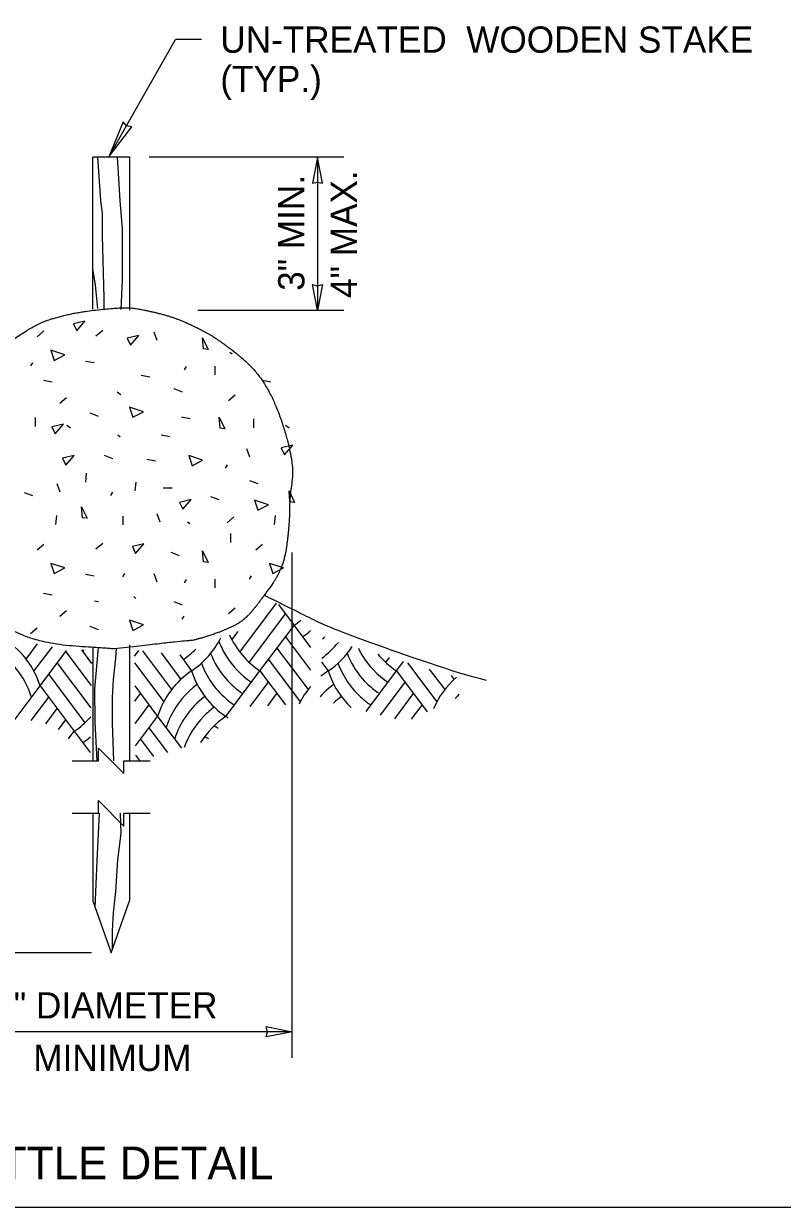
# Model space of a CAD drawing. Extents: x 99862 to 103680, y 99470 to 102076.
# Drawn here: x 100379 to 100841, y 100000 to 100721 of the extents above; entities that cross this region are included whole.
import ezdxf

# ---------------------------------------------------------------- set-up
doc = ezdxf.new("R2010")
doc.units = 0
for name, color, linetype in [('Level 1', 7, 'Continuous'), ('Level 13', 7, 'Continuous'), ('Level 15', 7, 'Continuous'), ('Level 2', 7, 'Continuous'), ('Level 20', 7, 'Continuous'), ('Level 4', 7, 'Continuous')]:
    doc.layers.add(name, color=color, linetype=linetype)

msp = doc.modelspace()

# ---------------------------------------------------------------- linework, layer by layer
at = {"layer": 'Level 1'}
msp.add_lwpolyline([(99862, 99999.5), (103151, 99999.5), (103151, 102075.5), (99862, 102075.5)], close=True, dxfattribs=at)
at = {"layer": 'Level 13'}
for p, q in [((100510.74, 100337.71), (100533.08, 100367.48)), ((100534.27, 100366.66), (100543.76, 100354.01)), ((100516.45, 100331.46), (100538.56, 100360.94)), ((100505.92, 100345.14), (100509.76, 100350.26)), ((100522.97, 100326.29), (100543.76, 100354.01)), ((100543.76, 100354.01), (100553.86, 100340.53)), ((100380.55, 100333.49), (100387.53, 100342.8)), ((100385.37, 100326.06), (100396.57, 100341)), ((100538.56, 100347.08), (100553.86, 100326.67)), ((100389.11, 100317.19), (100405.2, 100338.64)), ((100404.7, 100337.98), (100420.22, 100317.3)), ((100414.27, 100339.08), (100420.43, 100330.87)), ((100446.51, 100335.22), (100449.18, 100338.78)), ((100451.42, 100338.53), (100469.17, 100314.87)), ((100462.76, 100337.27), (100474.87, 100321.12)), ((100474.1, 100336.01), (100481.39, 100326.29)), ((100533.36, 100340.15), (100552.32, 100314.87)), ((100599.61, 100331.46), (100601.88, 100334.48)), ((100399.51, 100331.05), (100420, 100303.72)), ((100446.55, 100331.16), (100464.35, 100307.44)), ((100528.17, 100333.22), (100547.5, 100307.44)), ((100560.51, 100331.67), (100564.55, 100326.29)), ((100606.12, 100326.29), (100610.39, 100331.98)), ((100612.78, 100331.28), (100630.66, 100307.44)), ((100626.12, 100327.35), (100635.48, 100314.87)), ((100394.31, 100324.12), (100416.42, 100294.65)), ((100502.18, 100298.57), (100522.97, 100326.29)), ((100517.04, 100304.53), (100528.17, 100319.36)), ((100522.97, 100326.29), (100538.46, 100305.63)), ((100587.63, 100301.63), (100606.12, 100326.29)), ((100596.35, 100299.4), (100611.32, 100319.36)), ((100606.12, 100326.29), (100624.83, 100301.34)), ((100639.45, 100323.42), (100641.19, 100321.12)), ((100371.98, 100294.36), (100389.11, 100317.19)), ((100389.11, 100317.19), (100409.9, 100289.47)), ((100446.7, 100317.1), (100460.6, 100298.57)), ((100446.8, 100307.88), (100450.21, 100312.43)), ((100527.86, 100305.09), (100533.36, 100312.43)), ((100606.12, 100298.57), (100616.52, 100312.43)), ((100383.59, 100295.97), (100394.31, 100310.26)), ((100450.21, 100298.57), (100455.4, 100305.5)), ((100616.52, 100298.57), (100621.72, 100305.5)), ((100392.56, 100294.07), (100399.51, 100303.33)), ((100446.94, 100294.22), (100450.21, 100298.57)), ((100447.09, 100280.55), (100460.6, 100298.57)), ((100460.6, 100298.57), (100475.18, 100279.14)), ((100605.08, 100297.17), (100606.12, 100298.57)), ((100615.3, 100296.94), (100616.52, 100298.57)), ((100400.28, 100290.5), (100404.7, 100296.4)), ((100455.4, 100291.64), (100466.69, 100276.59)), ((100406.41, 100284.82), (100409.9, 100289.47)), ((100409.9, 100289.47), (100419.58, 100276.57)), ((100450.21, 100284.71), (100458.21, 100274.04)), ((100447.15, 100274.93), (100449.58, 100271.69))]:
    msp.add_line(p, q, dxfattribs=at)
for centre, start, end in [((100514.41, 100397.67), 303.90361, 309.64609), ((100552.31, 100369.95), 204.24471, 236.09639), ((100519.61, 100390.74), 303.90361, 310.62757), ((100338.98, 100301.25), 17.6434, 56.09639), ((100452.05, 100369.95), 303.90361, 333.41153), ((100547.12, 100363.02), 200.87781, 211.33197), ((100530, 100376.88), 305.57834, 320.80666), ((100524.81, 100383.81), 313.63976, 315.83303), ((100535.2, 100369.95), 303.90361, 326.80593), ((100333.78, 100294.32), 17.6434, 48.95975), ((100465.23, 100322.04), 161.09911, 162.3566), ((100446.85, 100376.88), 303.90361, 314.86242), ((100541.92, 100356.09), 201.43438, 220.94161), ((100547.12, 100363.02), 211.33188, 236.09639), ((100625.07, 100356.09), 201.43438, 220.94161), ((100630.27, 100363.02), 205.88324, 211.33197), ((100630.27, 100363.02), 211.33188, 236.09639), ((100635.47, 100369.95), 219.39613, 236.09639), ((100470.43, 100315.11), 161.84764, 162.3566), ((100536.72, 100349.16), 200.24322, 228.95992), ((100619.88, 100349.16), 200.24322, 228.95992), ((100510.74, 100282.62), 123.90361, 162.3566), ((100531.52, 100342.23), 197.6434, 236.09639), ((100541.92, 100356.09), 220.94154, 236.09639), ((100593.89, 100282.62), 123.90361, 129.91543), ((100614.68, 100342.23), 197.6434, 226.71979), ((100625.07, 100356.09), 220.94154, 236.09639), ((100677.05, 100282.62), 130.76183, 157.12727), ((100515.93, 100275.69), 126.30625, 154.2266), ((100593.89, 100282.62), 139.53727, 153.53859), ((100599.09, 100275.69), 126.30625, 138.64934), ((100521.13, 100268.76), 127.1006, 145.49109), ((100536.72, 100349.16), 228.95986, 236.09639), ((100604.29, 100268.76), 127.1006, 133.87218), ((100619.88, 100349.16), 228.95986, 236.09639), ((100682.24, 100275.69), 136.30424, 140.20496), ((100380.56, 100333.14), 303.90361, 318.4378), ((100515.93, 100275.69), 154.22654, 162.3566), ((100521.13, 100268.76), 145.49102, 162.3566), ((100526.33, 100261.83), 135.71269, 160.22849), ((100531.52, 100254.9), 123.90361, 148.19583), ((100526.33, 100261.83), 126.331, 135.71278), ((100472.83, 100254.9), 54.1392, 56.09634), ((100609.48, 100261.83), 126.331, 126.61289), ((100467.64, 100247.97), 55.25432, 58.54646), ((100385.75, 100326.21), 303.90361, 310.22759), ((100462.44, 100241.05), 56.37289, 59.30215)]:
    msp.add_arc(centre, 52.61, start, end, dxfattribs=at)
msp.add_open_spline([(100660.97, 100320.37), (100641.53, 100325.21), (100579.75, 100347.1), (100558.59, 100355.49), (100544.07, 100363.27), (100525.77, 100372.29)], degree=3, dxfattribs=at)
at = {"layer": 'Level 15'}
for p, q in [((100430.86, 100639.45), (100471.46, 100710.83)), ((100487.46, 100710.83), (100471.46, 100710.83)), ((100455.52, 100639.45), (100574.05, 100639.45)), ((100455.52, 100639.45), (100574.05, 100639.45)), ((100558.06, 100639.08), (100558.06, 100545.93)), ((100558.06, 100639.08), (100558.06, 100545.93)), ((100485.09, 100545.93), (100574.05, 100545.93)), ((100485.09, 100545.93), (100574.05, 100545.93)), ((100542.55, 100090.53), (100542.55, 100398.42)), ((100420.38, 100154.53), (100187.86, 100154.53)), ((100320.2, 100106.53), (100542.55, 100106.53))]:
    msp.add_line(p, q, dxfattribs=at)
for points in [[(100430.86, 100639.45), (100444.86, 100657.72), (100441.74, 100658.3), (100439.69, 100660.71)], [(100558.06, 100639.08), (100554.97, 100623.36), (100558.06, 100624.08), (100561.14, 100623.36)], [(100558.06, 100639.08), (100554.97, 100623.36), (100558.06, 100624.08), (100561.14, 100623.36)], [(100558.06, 100545.93), (100554.97, 100561.65), (100558.06, 100560.92), (100561.14, 100561.65)], [(100558.06, 100545.93), (100554.97, 100561.65), (100558.06, 100560.92), (100561.14, 100561.65)], [(100542.55, 100106.5), (100526.82, 100103.41), (100527.55, 100106.5), (100526.82, 100109.58)]]:
    msp.add_lwpolyline(points, close=True, dxfattribs=at)
for points in [[(100408.64, 100271.52), (100424.64, 100271.52), (100424.64, 100279.27), (100440.12, 100263.78), (100440.12, 100271.52), (100456.12, 100271.52)], [(100408.64, 100239.52), (100424.64, 100239.52), (100424.64, 100247.27), (100440.12, 100231.78), (100440.12, 100239.52), (100456.12, 100239.52)]]:
    msp.add_lwpolyline(points, dxfattribs=at)
at = {"layer": 'Level 2'}
for p, q in [((100387.28, 100529.82), (100391.38, 100533.34)), ((100387.28, 100529.82), (100391.38, 100533.34)), ((100423.1, 100530.37), (100427.2, 100533.88)), ((100423.1, 100530.37), (100427.2, 100533.88)), ((100460.39, 100527.48), (100458.58, 100532.57)), ((100460.39, 100527.48), (100458.58, 100532.57)), ((100384.47, 100513.99), (100383.34, 100512.02)), ((100384.47, 100513.99), (100383.34, 100512.02)), ((100416.69, 100515.05), (100422.01, 100514.08)), ((100416.69, 100515.05), (100422.01, 100514.08)), ((100504.67, 100520.47), (100506.08, 100519.34)), ((100504.67, 100520.47), (100506.08, 100519.34)), ((100477.95, 100511.74), (100476.82, 100509.77)), ((100477.95, 100511.74), (100476.82, 100509.77)), ((100495.54, 100511.99), (100495.54, 100506.59)), ((100495.54, 100511.99), (100495.54, 100506.59)), ((100391.19, 100503.37), (100396.5, 100502.4)), ((100391.19, 100503.37), (100396.5, 100502.4)), ((100450.61, 100506.36), (100455.93, 100505.39)), ((100450.61, 100506.36), (100455.93, 100505.39)), ((100524.34, 100503.37), (100529.65, 100502.4)), ((100524.34, 100503.37), (100529.65, 100502.4)), ((100401.12, 100489.36), (100405.22, 100492.88)), ((100401.12, 100489.36), (100405.22, 100492.88)), ((100435.95, 100496.26), (100438.2, 100494.57)), ((100435.95, 100496.26), (100438.2, 100494.57)), ((100470.61, 100498.33), (100475.63, 100496.32)), ((100470.61, 100498.33), (100475.63, 100496.32)), ((100503.88, 100490.99), (100507.98, 100494.51)), ((100503.88, 100490.99), (100507.98, 100494.51)), ((100386, 100480.54), (100386, 100475.14)), ((100386, 100480.54), (100386, 100475.14)), ((100419.41, 100483.4), (100424.43, 100481.39)), ((100419.41, 100483.4), (100424.43, 100481.39)), ((100475.13, 100480.98), (100480.44, 100480.01)), ((100475.13, 100480.98), (100480.44, 100480.01)), ((100519.15, 100479.79), (100519.15, 100474.39)), ((100519.15, 100479.79), (100519.15, 100474.39)), ((100405.29, 100475.99), (100407.54, 100474.3)), ((100405.29, 100475.99), (100407.54, 100474.3)), ((100538.44, 100475.99), (100540.69, 100474.3)), ((100436.51, 100470.07), (100437.92, 100468.95)), ((100436.51, 100470.07), (100437.92, 100468.95)), ((100462.74, 100470.02), (100468.05, 100469.06)), ((100462.74, 100470.02), (100468.05, 100469.06)), ((100428.1, 100457.6), (100433.11, 100455.59)), ((100428.1, 100457.6), (100433.11, 100455.59)), ((100516.74, 100456.46), (100514.92, 100461.55)), ((100516.74, 100456.46), (100514.92, 100461.55)), ((100454.08, 100455.31), (100459.39, 100454.34)), ((100454.08, 100455.31), (100459.39, 100454.34)), ((100502.99, 100451.77), (100501.86, 100449.8)), ((100502.99, 100451.77), (100501.86, 100449.8)), ((100417.22, 100446.7), (100416.69, 100441.33)), ((100417.22, 100446.7), (100416.69, 100441.33)), ((100516.58, 100442.19), (100521.66, 100440.38)), ((100516.58, 100442.19), (100521.66, 100440.38)), ((100379.32, 100434.85), (100384.41, 100433.03)), ((100379.32, 100434.85), (100384.41, 100433.03)), ((100401.27, 100435.14), (100399.46, 100440.23)), ((100401.27, 100435.14), (100399.46, 100440.23)), ((100433.14, 100435.15), (100432.01, 100433.18)), ((100433.14, 100435.15), (100432.01, 100433.18)), ((100447.49, 100441.3), (100446.82, 100435.94)), ((100447.49, 100441.3), (100446.82, 100435.94)), ((100464.07, 100437.86), (100469.47, 100437.86)), ((100464.07, 100437.86), (100469.47, 100437.86)), ((100492.86, 100432.61), (100497.88, 100430.61)), ((100492.86, 100432.61), (100497.88, 100430.61)), ((100399.04, 100420.91), (100398.51, 100415.53)), ((100399.04, 100420.91), (100398.51, 100415.53)), ((100439.49, 100420.58), (100439.49, 100415.18)), ((100439.49, 100420.58), (100439.49, 100415.18)), ((100462.21, 100416.96), (100460.39, 100422.05)), ((100462.21, 100416.96), (100460.39, 100422.05)), ((100532.19, 100420.91), (100531.66, 100415.53)), ((100532.19, 100420.91), (100531.66, 100415.53)), ((100478.79, 100417.13), (100480.2, 100416.01)), ((100478.79, 100417.13), (100480.2, 100416.01)), ((100503.11, 100416.48), (100507.06, 100420.15)), ((100503.11, 100416.48), (100507.06, 100420.15)), ((100505.04, 100409.89), (100505.04, 100404.49)), ((100505.04, 100409.89), (100505.04, 100404.49)), ((100387.28, 100400.03), (100391.38, 100403.54)), ((100387.28, 100400.03), (100391.38, 100403.54)), ((100423.1, 100400.57), (100427.2, 100404.08)), ((100423.1, 100400.57), (100427.2, 100404.08)), ((100468.71, 100398.67), (100473.73, 100396.67)), ((100468.71, 100398.67), (100473.73, 100396.67)), ((100520.43, 100400.03), (100524.53, 100403.54)), ((100520.43, 100400.03), (100524.53, 100403.54)), ((100416.69, 100385.25), (100422.01, 100384.28)), ((100416.69, 100385.25), (100422.01, 100384.28)), ((100440.45, 100385.6), (100439.33, 100383.63)), ((100440.45, 100385.6), (100439.33, 100383.63)), ((100460.39, 100380.24), (100458.58, 100385.32)), ((100460.39, 100380.24), (100458.58, 100385.32)), ((100517.62, 100384.19), (100516.49, 100382.22)), ((100517.62, 100384.19), (100516.49, 100382.22)), ((100477.95, 100381.94), (100476.82, 100379.97)), ((100477.95, 100381.94), (100476.82, 100379.97)), ((100495.54, 100382.2), (100495.54, 100376.8)), ((100495.54, 100382.2), (100495.54, 100376.8)), ((100391.19, 100373.57), (100396.5, 100372.61)), ((100391.19, 100373.57), (100396.5, 100372.61)), ((100446.08, 100371.53), (100447.49, 100370.4)), ((100446.08, 100371.53), (100447.49, 100370.4)), ((100401.12, 100359.57), (100405.22, 100363.08)), ((100401.12, 100359.57), (100405.22, 100363.08)), ((100424.7, 100368.43), (100422.17, 100368.71)), ((100424.7, 100368.43), (100422.17, 100368.71)), ((100470.61, 100368.53), (100475.63, 100366.53)), ((100470.61, 100368.53), (100475.63, 100366.53)), ((100503.88, 100361.2), (100507.98, 100364.71)), ((100503.88, 100361.2), (100507.98, 100364.71)), ((100476.54, 100359.7), (100475.41, 100357.73)), ((100476.54, 100359.7), (100475.41, 100357.73)), ((100383.18, 100349.09), (100387.28, 100352.6)), ((100383.18, 100349.09), (100387.28, 100352.6)), ((100419.41, 100353.6), (100424.43, 100351.59)), ((100419.41, 100353.6), (100424.43, 100351.59)), ((100443.52, 100342.09), (100443.52, 100271.52)), ((100443.52, 100342.09), (100443.52, 100271.52)), ((100421.24, 100340.82), (100421.24, 100271.52)), ((100421.24, 100340.82), (100421.24, 100271.52)), ((100421.24, 100239.52), (100421.24, 100186.23)), ((100421.24, 100239.52), (100421.24, 100186.23)), ((100443.52, 100239.52), (100443.52, 100186.23)), ((100443.52, 100239.52), (100443.52, 100186.23)), ((100421.24, 100186.23), (100432.38, 100154.53)), ((100432.38, 100154.53), (100443.52, 100186.23))]:
    msp.add_line(p, q, dxfattribs=at)
for points in [[(100421.24, 100546.63), (100421.24, 100639.45), (100443.52, 100639.45), (100443.52, 100545.93)], [(100421.24, 100546.63), (100421.24, 100639.45), (100443.52, 100639.45), (100443.52, 100545.93)], [(100426.04, 100612.77), (100424.22, 100639.45)], [(100426.04, 100612.77), (100424.22, 100639.45)], [(100437.89, 100612.77), (100436.31, 100639.45)], [(100437.89, 100612.77), (100436.31, 100639.45)], [(100428.02, 100547.1), (100428.02, 100553.44), (100427.08, 100591.33), (100427.08, 100604.82), (100426.04, 100612.77)], [(100428.02, 100547.1), (100428.02, 100553.44), (100427.08, 100591.33), (100427.08, 100604.82), (100426.04, 100612.77)], [(100438.38, 100546.52), (100439.3, 100564.34), (100439.3, 100595.48), (100437.89, 100612.77)], [(100438.38, 100546.52), (100439.3, 100564.34), (100439.3, 100595.48), (100437.89, 100612.77)], [(100424.21, 100546.94), (100422.84, 100561.22), (100421.24, 100571.24)], [(100424.21, 100546.94), (100422.84, 100561.22), (100421.24, 100571.24)], [(100422.72, 100294.75), (100422.37, 100315.28), (100424.71, 100340.57)], [(100422.72, 100294.75), (100422.37, 100315.28), (100424.71, 100340.57)], [(100434.01, 100271.52), (100433.24, 100294.52), (100433.24, 100310.09), (100433.71, 100320.99), (100435.12, 100333.97), (100435.57, 100340.09)], [(100434.01, 100271.52), (100433.24, 100294.52), (100433.24, 100310.09), (100433.71, 100320.99), (100435.12, 100333.97), (100435.57, 100340.09)], [(100423.93, 100271.52), (100422.72, 100294.77)], [(100423.93, 100271.52), (100422.72, 100294.77)], [(100422.71, 100182.07), (100423.78, 100210.57), (100425.29, 100239.52)], [(100422.71, 100182.07), (100423.78, 100210.57), (100425.29, 100239.52)], [(100433.24, 100156.97), (100433.24, 100168.01), (100433.71, 100178.91), (100435.12, 100191.89), (100436.53, 100211.09), (100438.41, 100227.18), (100437.98, 100239.52)]]:
    msp.add_lwpolyline(points, dxfattribs=at)
for points in [[(100409.39, 100537.67), (100411.36, 100533.45), (100416.43, 100539.36)], [(100442.14, 100528.91), (100444.11, 100524.69), (100449.18, 100530.6)], [(100442.14, 100528.91), (100444.11, 100524.69), (100449.18, 100530.6)], [(100488.08, 100529.19), (100491.45, 100522.16), (100488.64, 100522.44)], [(100488.08, 100529.19), (100491.45, 100522.16), (100488.64, 100522.44)], [(100395.72, 100521.59), (100397.69, 100515.4), (100404.16, 100518.78)], [(100395.72, 100521.59), (100397.69, 100515.4), (100404.16, 100518.78)], [(100443.55, 100486.96), (100445.52, 100480.77), (100451.99, 100484.15)], [(100443.55, 100486.96), (100445.52, 100480.77), (100451.99, 100484.15)], [(100498.24, 100480.84), (100501.61, 100473.81), (100498.8, 100474.09)], [(100498.24, 100480.84), (100501.61, 100473.81), (100498.8, 100474.09)], [(100396.24, 100474.86), (100398.21, 100470.64), (100403.28, 100476.55)], [(100535.9, 100462.19), (100537.87, 100457.97), (100542.94, 100463.88)], [(100535.9, 100462.19), (100537.87, 100457.97), (100542.94, 100463.88)], [(100402.75, 100455.81), (100404.72, 100451.59), (100409.79, 100457.5)], [(100402.75, 100455.81), (100404.72, 100451.59), (100409.79, 100457.5)], [(100479.63, 100457.4), (100481.6, 100451.21), (100488.08, 100454.59)], [(100479.63, 100457.4), (100481.6, 100451.21), (100488.08, 100454.59)], [(100540.69, 100436), (100544.06, 100428.96), (100541.25, 100429.24)], [(100540.69, 100436), (100544.06, 100428.96), (100541.25, 100429.24)], [(100474.01, 100428.96), (100475.98, 100424.74), (100481.04, 100430.65)], [(100474.01, 100428.96), (100475.98, 100424.74), (100481.04, 100430.65)], [(100519.69, 100430.29), (100521.66, 100424.1), (100528.13, 100427.48)], [(100414.33, 100426.28), (100417.71, 100419.25), (100414.89, 100419.53)], [(100414.33, 100426.28), (100417.71, 100419.25), (100414.89, 100419.53)], [(100445.28, 100402.05), (100447.25, 100397.83), (100452.31, 100403.74)], [(100445.28, 100402.05), (100447.25, 100397.83), (100452.31, 100403.74)], [(100488.08, 100399.4), (100491.45, 100392.36), (100488.64, 100392.64)], [(100488.08, 100399.4), (100491.45, 100392.36), (100488.64, 100392.64)], [(100395.72, 100391.8), (100397.69, 100385.6), (100404.16, 100388.98)], [(100395.72, 100391.8), (100397.69, 100385.6), (100404.16, 100388.98)], [(100528.87, 100391.8), (100530.84, 100385.6), (100537.31, 100388.98)], [(100528.87, 100391.8), (100530.84, 100385.6), (100537.31, 100388.98)], [(100443.55, 100357.17), (100445.52, 100350.97), (100451.99, 100354.35)], [(100443.55, 100357.17), (100445.52, 100350.97), (100451.99, 100354.35)]]:
    msp.add_lwpolyline(points, close=True, dxfattribs=at)
at = {"layer": 'Level 4'}
msp.add_open_spline([(100434.17, 100339.7), (100478.39, 100344.74), (100482.61, 100344.74), (100500.08, 100350.29), (100513.18, 100356.68), (100523.15, 100368.77), (100537.35, 100388.82), (100540.94, 100414.87), (100540.94, 100431.03), (100544.24, 100454.44), (100527.43, 100503.98), (100498.1, 100528.38), (100480, 100537.76), (100466.56, 100543), (100447.52, 100547.2), (100438.61, 100547.76), (100407.12, 100544.39), (100381.94, 100535.95), (100348.95, 100508.78), (100332.83, 100489.47), (100318.41, 100440.52), (100327.97, 100372.94), (100362.65, 100355.11), (100390.35, 100342.64), (100434.17, 100339.7), (100434.17, 100339.7)], degree=2, dxfattribs=at)

# ---------------------------------------------------------------- texts
at = {"layer": 'Level 20'}
for s, height, p in [('UN-TREATED  WOODEN STAKE', 16, (100498.86, 100702.84)), ('(TYP.)', 16, (100498.86, 100678.84)), ('WATTLE DETAIL', 20, (100321.59, 100016.53))]:
    msp.add_text(s, height=height, dxfattribs=at).set_placement(p)
for s, rotation, p in [('3" MIN.', 90, (100550.06, 100557.8)), ('3" MIN.', 90, (100550.06, 100557.8)), ('4" MAX.', 90, (100582.05, 100553.45)), ('4" MAX.', 90, (100582.05, 100553.45)), ('8" DIAMETER', 360, (100361.14, 100114.53)), (' MINIMUM', 360, (100379.02, 100082.53))]:
    msp.add_text(s, height=16, rotation=rotation, dxfattribs=at).set_placement(p)

doc.saveas('drawing.dxf')
